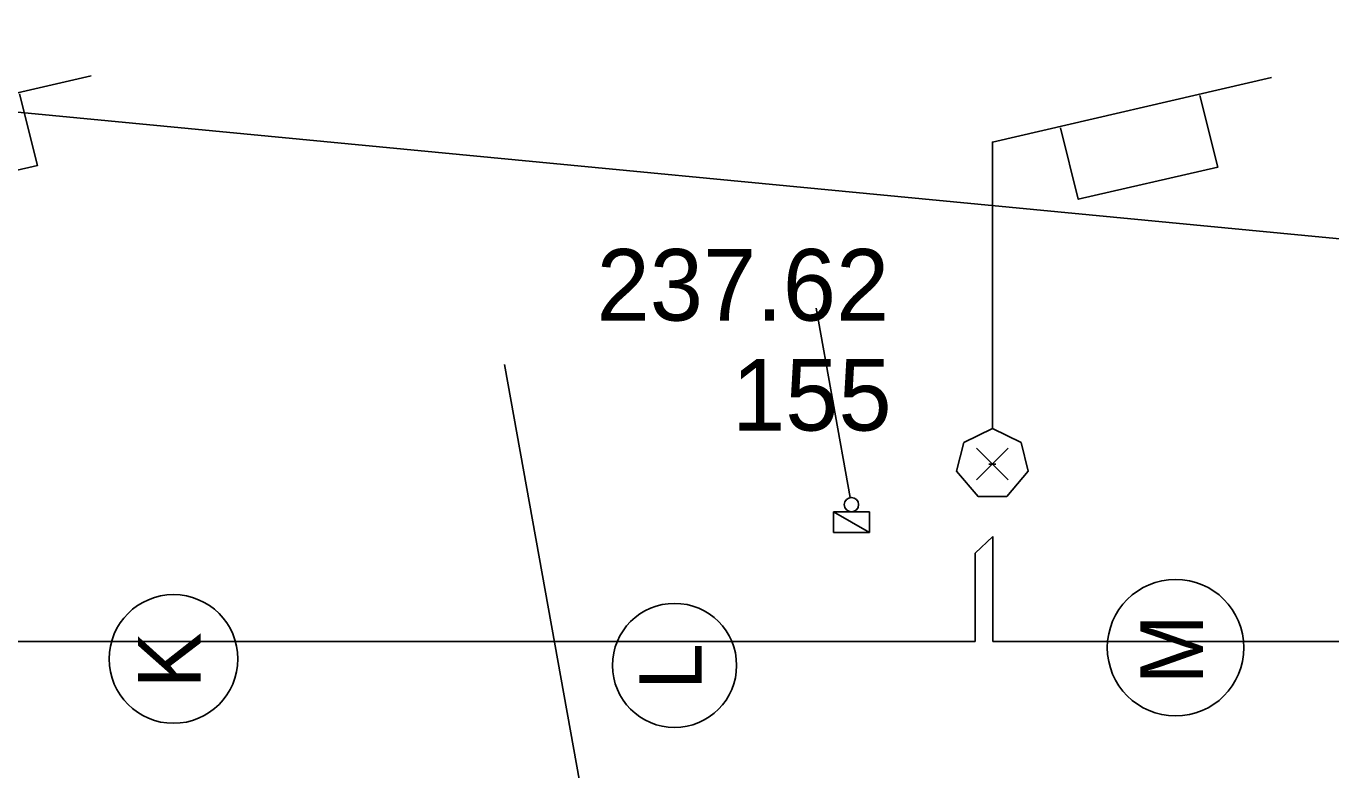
# Model space of a CAD drawing. Extents: x -264222 to -263592, y -1242345 to -1242048.
# Drawn here: x -263850.59 to -263832.36, y -1242082.09 to -1242071.7 of the extents above; entities that cross this region are included whole.
import ezdxf

# ---------------------------------------------------------------- set-up
doc = ezdxf.new("R2010")
doc.units = 0
for name, color, linetype in [('BOD_CISLO', 7, 'Continuous'), ('BOD_SYMBOL', 7, 'Continuous'), ('BOD_VYSKA', 7, 'Continuous'), ('HESCON_OSI_STAVBY_KFA', 7, 'Continuous'), ('KFA_2D_SITUACIA_DSP', 7, 'Continuous'), ('KFA_SO_62-1_VO_LAMPY_MERANE', 7, 'Continuous'), ('KFA_SO_62-1_VO_TRASA_KABLOV_PROJEKT', 7, 'Continuous')]:
    doc.layers.add(name, color=color, linetype=linetype)

msp = doc.modelspace()

# ---------------------------------------------------------------- linework, layer by layer
at = {"layer": 'BOD_SYMBOL'}
for p, q in [((-263837.308, -1242078.044), (-263836.866, -1242077.602)), ((-263836.866, -1242078.044), (-263837.308, -1242077.602))]:
    msp.add_line(p, q, dxfattribs=at)
at = {"layer": 'HESCON_OSI_STAVBY_KFA'}
for centre, radius in [((-263834.528, -1242080.387), 0.954), ((-263848.528, -1242080.545), 0.899), ((-263841.528, -1242080.635), 0.867)]:
    msp.add_circle(centre, radius, dxfattribs=at)
at = {"layer": 'KFA_2D_SITUACIA_DSP'}
for p, q in [((-263765.366, -1242081.09), (-263864.57, -1242071.577)), ((-263839.074, -1242078.29), (-263839.551, -1242075.646)), ((-263841.881, -1242087.633), (-263843.905, -1242076.433)), ((-263839.306, -1242078.779), (-263839.306, -1242078.489)), ((-263839.306, -1242078.489), (-263838.806, -1242078.489)), ((-263838.806, -1242078.779), (-263839.306, -1242078.489)), ((-263838.806, -1242078.779), (-263839.306, -1242078.489)), ((-263839.306, -1242078.489), (-263839.306, -1242078.779)), ((-263838.806, -1242078.489), (-263838.806, -1242078.779)), ((-263838.806, -1242078.779), (-263839.306, -1242078.779)), ((-263839.306, -1242078.779), (-263838.806, -1242078.779))]:
    msp.add_line(p, q, dxfattribs=at)
msp.add_circle((-263839.056, -1242078.389), 0.1, dxfattribs=at)
at = {"layer": 'KFA_SO_62-1_VO_LAMPY_MERANE'}
for p, q in [((-263837.137, -1242077.823), (-263837.037, -1242077.823)), ((-263837.087, -1242077.823), (-263837.087, -1242077.823))]:
    msp.add_line(p, q, dxfattribs=at)
for points in [[(-263853.578, -1242077.299), (-263853.978, -1242077.499), (-263854.078, -1242077.899), (-263853.778, -1242078.249), (-263853.378, -1242078.249), (-263853.078, -1242077.899), (-263853.178, -1242077.499), (-263853.578, -1242077.299), (-263853.578, -1242073.299), (-263849.678, -1242072.399)], [(-263837.087, -1242077.323), (-263837.487, -1242077.523), (-263837.587, -1242077.923), (-263837.287, -1242078.273), (-263836.887, -1242078.273), (-263836.587, -1242077.923), (-263836.687, -1242077.523), (-263837.087, -1242077.323), (-263837.087, -1242073.323), (-263833.187, -1242072.423)], [(-263850.678, -1242072.649), (-263850.428, -1242073.649), (-263852.378, -1242074.099), (-263852.628, -1242073.099)], [(-263834.187, -1242072.673), (-263833.937, -1242073.673), (-263835.887, -1242074.123), (-263836.137, -1242073.123)]]:
    msp.add_lwpolyline(points, dxfattribs=at)
at = {"layer": 'KFA_SO_62-1_VO_TRASA_KABLOV_PROJEKT'}
for p, q in [((-263837.08, -1242078.835), (-263837.33, -1242079.065)), ((-263837.08, -1242080.303), (-263837.08, -1242078.835)), ((-263837.33, -1242079.065), (-263837.33, -1242080.303)), ((-263837.33, -1242080.303), (-263853.59, -1242080.303)), ((-263814.314, -1242080.303), (-263837.08, -1242080.303))]:
    msp.add_line(p, q, dxfattribs=at)

# ---------------------------------------------------------------- texts
at = {"layer": 'BOD_CISLO'}
msp.add_text('155', height=1, dxfattribs=at).set_placement((-263840.726, -1242077.354))
at = {"layer": 'BOD_VYSKA'}
msp.add_text('237.62', height=1, dxfattribs=at).set_placement((-263842.618, -1242075.818))
at = {"layer": 'HESCON_OSI_STAVBY_KFA'}
for s, p in [('M', (-263834.147, -1242080.896)), ('K', (-263848.147, -1242080.952)), ('L', (-263841.147, -1242080.975))]:
    msp.add_text(s, height=0.875, rotation=90, dxfattribs=at).set_placement(p)

doc.saveas('drawing.dxf')
